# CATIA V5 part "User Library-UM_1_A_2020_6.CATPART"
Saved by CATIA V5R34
Part number: 7D37CFB8-28AF-4AE6-9052-58D53263B79B.1
Revision: ANY
Definition: UNKNOWN
Nomenclature: 7D37CFB8-28AF-4AE6-9052-58D53263B79B
Source: Unknown
Bounding box of the stored display mesh (mm): x 34.376 to 54.376, y 70.124 to 90.124, z 0 to 250
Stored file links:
  C:\Users\Apolinar\Desktop\cnc\User Library-UM_1_A_2020_6.CATPART
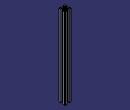
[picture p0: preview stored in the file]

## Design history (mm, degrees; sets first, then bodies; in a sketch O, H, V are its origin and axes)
Set1
  Sketch1 on face of Solid1, origin (54.3765, 0, 0), H (0, 1, 0), V (0, 0, 1)
    line L1 (70.1241, 1000) -> (90.1241, 1000)
    line L2 (90.1241, 1000) -> (90.1241, 250)
    line L3 (90.1241, 250) -> (70.1241, 250)
    line L4 (70.1241, 250) -> (70.1241, 1000)
    reference projected line E1 (90.1241, 1000) -> (90.1241, 0) from edge [face of Solid1 | face of Solid1]
    reference projected line E2 (70.1241, 1000) -> (70.1241, 0) from edge [face of Solid1 | face of Solid1]
    reference projected point E3 (83.8741, 1000) from vertex [face of Solid1 | face of Solid1 | face of Solid1]
    distance L3 H = 250
    horizontal: L1 H, L3 H
    vertical: L2 V, L4 V
    coincidence: E1 L2, E2 L4, L1 E3
Body1 "NONE" (main body)
  Solid1: solid without history
  Pocket1: profile Sketch1, direction (-1, 0, 0), length 20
